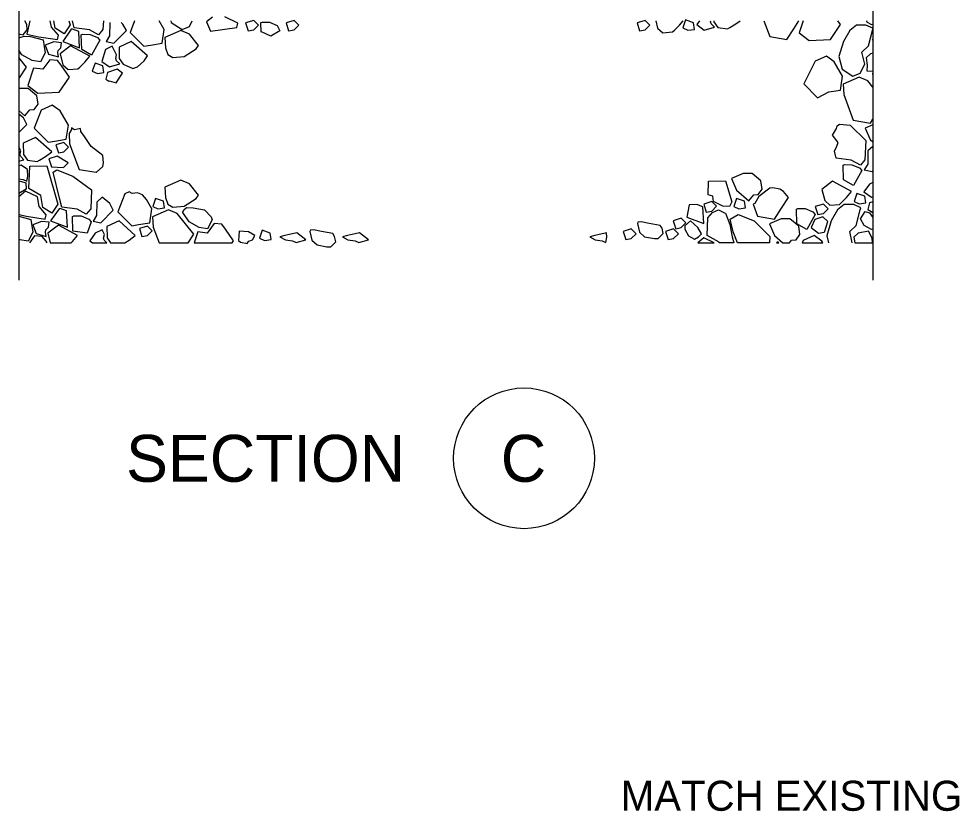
# Model space of a CAD drawing. Extents: x 99862 to 103151, y 100000 to 108153.
# Drawn here: x 101790 to 102291, y 101094 to 101517 of the extents above; entities that cross this region are included whole.
import ezdxf

# ---------------------------------------------------------------- set-up
doc = ezdxf.new("R2010")
doc.units = 0
for name, color, linetype in [('Level 15', 7, 'Continuous'), ('Level 18', 7, 'Continuous'), ('Level 20', 7, 'Continuous')]:
    doc.layers.add(name, color=color, linetype=linetype)

msp = doc.modelspace()

# ---------------------------------------------------------------- linework, layer by layer
at = {"layer": 'Level 15'}
for points in [[(102245.17, 101887.78), (102245.17, 101714.5), (102260.65, 101714.5), (102229.68, 101683.53), (102245.17, 101683.53), (102245.17, 101377.32)], [(101790.17, 101558.07), (101790.17, 101377.32)]]:
    msp.add_lwpolyline(points, dxfattribs=at)
at = {"layer": 'Level 20'}
for p, q in [((102171.05, 101397.32), (102163.29, 101397.32)), ((102190.13, 101397.32), (102172.98, 101397.32))]:
    msp.add_line(p, q, dxfattribs=at)
for points in [[(101790.17, 101508.09), (101790.95, 101508.49), (101792.54, 101508.15), (101794.64, 101510.7), (101794.46, 101513.7), (101793.37, 101515.66)], [(101796.01, 101515.66), (101794.48, 101508.49), (101800.86, 101507.12), (101810.7, 101505.57), (101811.29, 101507.86), (101807.5, 101512.24), (101806.95, 101515.66)], [(101816.87, 101515.66), (101817.48, 101513.51), (101814.37, 101508.63), (101809.5, 101511.74), (101808.86, 101515.66)], [(101835.24, 101515.66), (101835, 101510.95), (101832.65, 101508.1), (101827.78, 101510.84), (101819.7, 101511.89), (101818.74, 101515.66)], [(101838.59, 101514.62), (101838.56, 101507.63), (101836.69, 101504.53), (101840.84, 101503.7), (101847.47, 101510.4), (101845.62, 101513.87), (101844.74, 101514.62)], [(101851.86, 101515.66), (101849.45, 101509.4), (101856.84, 101502.01), (101860.39, 101502.6), (101866.55, 101503.63), (101867.63, 101511.03), (101864.96, 101515.66)], [(101871.15, 101515.66), (101871.38, 101514.77), (101877.14, 101510.92), (101881.06, 101512.62), (101882.58, 101515.66)], [(101893.28, 101517.59), (101890.07, 101515.03), (101892.31, 101510.11), (101906.3, 101512.11), (101906.89, 101514.4), (101899.92, 101517.62)], [(101915.29, 101510.77), (101917.81, 101513.29), (101915.29, 101515.8), (101911.01, 101514.47), (101912.34, 101510.18), (101912.34, 101510.18), (101915.29, 101510.77)], [(101919.19, 101509.57), (101919.04, 101514.65), (101919.78, 101514.94)], [(101919.78, 101514.94), (101923.7, 101514.92), (101927.76, 101513.17), (101929.3, 101510.32), (101924.5, 101507.47), (101919.42, 101509.69)], [(101936.88, 101510.77), (101939.39, 101513.29), (101936.88, 101515.8), (101932.59, 101514.47), (101933.92, 101510.18), (101933.92, 101510.18), (101936.88, 101510.77)], [(102123.79, 101510.77), (102126.3, 101513.29), (102123.79, 101515.8), (102119.5, 101514.47), (102120.83, 101510.18), (102120.83, 101510.18), (102123.79, 101510.77)], [(102129.44, 101515.66), (102130.42, 101511.7), (102133.19, 101509.22), (102138.36, 101509.67), (102139.43, 101510.59), (102142.09, 101513.25), (102144.11, 101515.66)], [(102146.62, 101510.52), (102150.13, 101511.04), (102149.61, 101514.55), (102145.38, 101516.04), (102143.89, 101511.81), (102143.89, 101511.81), (102146.62, 101510.52)], [(102152.81, 101515.66), (102151.28, 101513.57), (102155.3, 101510.61), (102160.73, 101512.27), (102159.06, 101513.97), (102158.66, 101515.07), (102158.79, 101515.66)], [(102160.49, 101515.66), (102160.49, 101515.11), (102162.63, 101512.07), (102167.77, 101511.32), (102169.02, 101511.97), (102172.22, 101513.96), (102174.48, 101515.66)], [(102187.02, 101515.66), (102190.2, 101507.14), (102199.29, 101505.59), (102202.98, 101511.36), (102205.74, 101515.66)], [(102208, 101515.66), (102205.79, 101509.14), (102211.19, 101505.07), (102222.49, 101505.59), (102227.96, 101513.58), (102226.52, 101515.66)], [(102241.9, 101515.66), (102241.67, 101514.99), (102241.67, 101514.99), (102244.4, 101513.71)], [(101885.87, 101502.52), (101881.09, 101508.51), (101876.5, 101510.43), (101868, 101506.67), (101868.3, 101501.2), (101869.61, 101497.68)], [(102245.17, 101511.65), (102241.45, 101513.24), (102236.38, 101513.28), (102232.83, 101510.48), (102229.43, 101504.56), (102227.07, 101496.58), (102228.77, 101489.86), (102234.53, 101486.01), (102238.45, 101487.71), (102240.82, 101492.44), (102239.34, 101498.95), (102242.74, 101502.2), (102244.97, 101510.51), (102245.17, 101511.39)], [(102244.4, 101513.71), (102245.17, 101513.82)], [(101790.17, 101506.58), (101793, 101507.38), (101796.32, 101507.16), (101803.12, 101505.38), (101803.64, 101501.98), (101804.16, 101498.58), (101801.64, 101493.78), (101797.21, 101494.52), (101791.81, 101497.47), (101790.17, 101500.02)], [(101824.18, 101508.4), (101828.1, 101508.38), (101832.16, 101506.63), (101833.41, 101505.22), (101828.91, 101497.32), (101823.68, 101500.24), (101823.44, 101508.11), (101824.18, 101508.4)], [(102245.17, 101505.36), (102245.03, 101505.6), (102245.17, 101505.81)], [(101869.61, 101497.68), (101872.15, 101496.12), (101878.3, 101496.55), (101884.59, 101500.73), (101885.87, 101502.52)], [(101790.17, 101484.54), (101790.59, 101485.2), (101794.28, 101490.96), (101790.17, 101496.12)], [(102245.17, 101498.29), (102243.88, 101498.02), (102241.59, 101495.95), (102242.11, 101492.04), (102241.96, 101488.86), (102245.14, 101488.71), (102245.17, 101488.72)], [(101832, 101487.55), (101835.52, 101488.07), (101835, 101491.58), (101830.76, 101493.07), (101829.27, 101488.83), (101829.27, 101488.83), (101832, 101487.55)], [(101845.49, 101487.69), (101842.57, 101489.75), (101837.47, 101488.05), (101836.51, 101484.43), (101838.16, 101483.51)], [(101838.16, 101483.51), (101838.26, 101483.58), (101842.03, 101482.58), (101845.49, 101487.69)], [(102245.17, 101480.16), (102242.41, 101483.6), (102237.83, 101485.52), (102229.33, 101481.75), (102229.63, 101476.29), (102234.73, 101462.61), (102243.82, 101461.06), (102245.17, 101463.16)], [(102245.17, 101486.94), (102245.08, 101487.64), (102245.17, 101487.66)], [(101790.17, 101467.75), (101793.32, 101465.02), (101795.97, 101468.08), (101798.35, 101468.42), (101800.42, 101471.23), (101799.82, 101475.66), (101795.09, 101479.51), (101790.36, 101479.51), (101790.17, 101479.42)], [(101790.17, 101456.05), (101794.43, 101460.36), (101792.59, 101463.83), (101790.17, 101465.9)], [(102224.62, 101446.14), (102225.95, 101448.71), (102226.73, 101450.82), (102223.63, 101454.65), (102225.74, 101458.13), (102226.1, 101459.67), (102227.37, 101460.52)], [(102227.37, 101460.52), (102232.97, 101459.9), (102241.37, 101451.76), (102240.86, 101441.51), (102238.51, 101438.66), (102233.64, 101441.4), (102225.55, 101442.45), (102224.62, 101446.14)], [(102245.17, 101460.22), (102241.08, 101458.47), (102243.74, 101452.27), (102245.17, 101451.04)], [(101818.25, 101457.64), (101816.93, 101455.6), (101817.23, 101450.13), (101822.33, 101436.45), (101831.42, 101434.9), (101831.5, 101435.03)], [(101831.5, 101435.03), (101834.96, 101437.92), (101835.23, 101439.91), (101834.9, 101443.89), (101828.71, 101448.64), (101825.09, 101453.92), (101823.28, 101456.66), (101823.11, 101458.21), (101819.88, 101457.48), (101818.32, 101458.53), (101818.25, 101457.64)], [(101814.2, 101445.77), (101816.71, 101448.28), (101814.2, 101450.79), (101809.91, 101449.46), (101811.24, 101445.18), (101811.24, 101445.18), (101814.2, 101445.77)], [(101790.17, 101440.76), (101792.86, 101441.59), (101791.19, 101443.28), (101790.79, 101444.39), (101791.21, 101446.33), (101790.17, 101448.43)], [(102245.17, 101448.66), (102242.49, 101446.28), (102242.45, 101439.23), (102240.58, 101436.12), (102244.73, 101435.29), (102245.17, 101435.73)], [(101813.95, 101437.42), (101816.46, 101439.94), (101810.52, 101443.45), (101806.23, 101442.12), (101807.57, 101437.84), (101807.57, 101437.84), (101813.83, 101437.37)], [(101790.17, 101431.32), (101792.54, 101430.99), (101794.49, 101430.14), (101794.98, 101432.84), (101794.75, 101436.39), (101791.5, 101438.68), (101790.17, 101438.24)], [(102230.03, 101438.96), (102233.96, 101438.93), (102238.02, 101437.19), (102239.26, 101435.78), (102234.76, 101427.88), (102229.54, 101430.8), (102229.3, 101438.67), (102230.03, 101438.96)], [(101790.17, 101429.78), (101791.1, 101430.07), (101793.94, 101429.22), (101794.16, 101425.89), (101790.17, 101423.52)], [(101885.87, 101422.73), (101881.09, 101428.72), (101876.5, 101430.64), (101868, 101426.87), (101868.3, 101421.41), (101869.61, 101417.89)], [(102157.31, 101422.9), (102157.56, 101430.11), (102166.72, 101430.41), (102169.94, 101419.06)], [(102245.17, 101429.47), (102243.29, 101428.54), (102240.34, 101424.51), (102244.36, 101421.55), (102245.17, 101421.8)], [(101790.17, 101412.41), (101794.32, 101411.52), (101804.16, 101409.97), (101804.75, 101412.26), (101800.96, 101416.64), (101800.13, 101421.83), (101793.7, 101424.86), (101790.17, 101421.86)], [(101848.92, 101424.45), (101846.61, 101423.41), (101842.91, 101413.8), (101850.31, 101406.41), (101853.85, 101407), (101860.01, 101408.03), (101861.1, 101415.43), (101858.27, 101420.33)], [(101858.27, 101420.33), (101856.06, 101422.81), (101853.42, 101423.98), (101850.64, 101423.61), (101848.92, 101424.45)], [(102197.59, 101424.71), (102195.64, 101425.91), (102191.84, 101426.6), (102190.17, 101426.47), (102184.46, 101421.94), (102182.17, 101418.18), (102181.3, 101417.87)], [(102181.3, 101417.87), (102183.66, 101411.54), (102192.75, 101409.99), (102196.44, 101415.76), (102200.14, 101421.52), (102197.59, 101424.71)], [(101864.24, 101415.41), (101867.75, 101415.93), (101867.23, 101419.45), (101863, 101420.93), (101861.51, 101416.7), (101861.51, 101416.7), (101864.24, 101415.41)], [(101869.61, 101417.89), (101872.15, 101416.33), (101878.3, 101416.76), (101884.59, 101420.94), (101885.87, 101422.73)], [(102159.38, 101414.25), (102161.89, 101416.76), (102159.38, 101419.27), (102155.09, 101417.94), (102156.42, 101413.66), (102156.42, 101413.66), (102159.38, 101414.25)], [(102169.94, 101419.06), (102168.72, 101416.66), (102165.15, 101416.91), (102160.2, 101419.39), (102159.92, 101422.17), (102157.31, 101422.9)], [(102173.8, 101415.41), (102177.31, 101415.93), (102176.79, 101419.45), (102172.56, 101420.93), (102171.07, 101416.7), (102171.07, 101416.7), (102173.8, 101415.41)], [(102237.86, 101418.11), (102241.37, 101418.63), (102240.85, 101422.14), (102236.62, 101423.63), (102235.13, 101419.39), (102235.13, 101419.39), (102237.86, 101418.11)], [(102245.17, 101419.22), (102243.33, 101418.61), (102242.37, 101414.99), (102245.17, 101413.43)], [(101880.4, 101397.32), (101883.34, 101401.9), (101874.55, 101412.91), (101869.96, 101414.84), (101861.46, 101411.07), (101861.76, 101405.6), (101864.85, 101397.32)], [(101877.6, 101413.63), (101878.14, 101414.94), (101879.46, 101416.17), (101883, 101415.86), (101889.14, 101414.83), (101892.65, 101411.18), (101893.2, 101409.49)], [(102157.21, 101410.58), (102159.76, 101413.44), (102162.99, 101414.87), (102166.48, 101413.08), (102166.58, 101413.1)], [(102205.16, 101415.54), (102209.09, 101415.51), (102213.14, 101413.76), (102214.39, 101412.35), (102209.89, 101404.45), (102204.66, 101407.37), (102204.42, 101415.24), (102205.16, 101415.54)], [(102218.75, 101412.93), (102221.26, 101415.45), (102218.75, 101417.96), (102214.46, 101416.63), (102215.79, 101412.34), (102215.79, 101412.34), (102218.75, 101412.93)], [(102238.68, 101416.03), (102234.91, 101417.64), (102229.84, 101417.69), (102226.29, 101414.88), (102222.89, 101408.96), (102220.53, 101400.98), (102221.46, 101397.32)], [(102234.17, 101397.32), (102232.8, 101403.35), (102236.2, 101406.6), (102238.43, 101414.91), (102238.68, 101416.03)], [(101790.17, 101411.46), (101796.58, 101409.78), (101797.1, 101406.38), (101797.62, 101402.98), (101795.1, 101398.18), (101790.67, 101398.92), (101790.17, 101399.2)], [(101819.5, 101411.66), (101823.43, 101411.63), (101827.49, 101409.89), (101828.73, 101408.47), (101826.59, 101402.46), (101819, 101403.49), (101818.76, 101411.37), (101819.5, 101411.66)], [(101893.2, 101409.49), (101890.7, 101404.72), (101886.27, 101405.46), (101880.87, 101408.41), (101877.62, 101413.44), (101877.6, 101413.63)], [(102143.06, 101405.4), (102145.58, 101407.91), (102143.06, 101410.43), (102138.78, 101409.09), (102140.11, 101404.81), (102140.11, 101404.81), (102143.06, 101405.4)], [(102163.29, 101397.32), (102163.25, 101397.58), (102156.89, 101401.28), (102157.21, 101410.58)], [(102166.58, 101413.1), (102168.88, 101406.98), (102170.13, 101400.55), (102171.05, 101397.32)], [(102172.98, 101397.32), (102170.73, 101403.19), (102169.04, 101409.84), (102173.37, 101412.39), (102181.97, 101409.07), (102190.3, 101400.69), (102190.13, 101397.32)], [(102200.68, 101397.32), (102201.82, 101398.64), (102204.2, 101398.98), (102206.27, 101401.79), (102205.68, 101406.22), (102200.95, 101410.07), (102196.22, 101410.07), (102190.01, 101407.4), (102192.67, 101401.2), (102197.17, 101397.32)], [(102219.43, 101402.97), (102221.06, 101408.61), (102218.55, 101411.12), (102214.26, 101409.79), (102212.26, 101405.5), (102216.2, 101402.44), (102219.16, 101403.03)], [(102245.17, 101404.65), (102244.33, 101404.46), (102240.48, 101406.45), (102238.49, 101410), (102241.11, 101414.03), (102243.4, 101413.29), (102245.14, 101410.81), (102245.17, 101410.82)], [(101818.04, 101397.32), (101818.75, 101398.03), (101821.43, 101401.23), (101811.23, 101406.73), (101805.64, 101402.36), (101806.87, 101397.32)], [(101837.13, 101397.32), (101835.72, 101398.75), (101835.32, 101399.86), (101835.74, 101401.8), (101834.55, 101404.19), (101830.9, 101402.38), (101827.94, 101398.35), (101829.35, 101397.32)], [(101846.59, 101397.32), (101848.88, 101398.74), (101852.22, 101401.24), (101843.54, 101408.93), (101837.09, 101405.94), (101837.16, 101399.89), (101838.96, 101397.32)], [(101858.73, 101401.24), (101861.24, 101403.75), (101858.73, 101406.26), (101854.44, 101404.93), (101855.77, 101400.65), (101855.77, 101400.65), (101858.73, 101401.24)], [(101903.9, 101397.32), (101904.62, 101398.36), (101900.27, 101404.64), (101898.27, 101407.16), (101894.21, 101407.59), (101890.44, 101402.49), (101885.56, 101403.08), (101883.6, 101397.32)], [(101958.42, 101400.7), (101957.44, 101402.27), (101951.47, 101403.32), (101947.19, 101404.14), (101945.52, 101404.01), (101945.23, 101403.27)], [(102116.44, 101399.64), (102118.96, 101402.16), (102116.44, 101404.67), (102112.16, 101403.34), (102113.49, 101399.05), (102113.49, 101399.05), (102116.44, 101399.64)], [(102132.86, 101405.04), (102131.88, 101406.61), (102125.92, 101407.66), (102121.64, 101408.48), (102119.96, 101408.35), (102119.67, 101407.61)], [(102119.67, 101407.61), (102120.8, 101403.02), (102123.57, 101400.54), (102128.74, 101399.52), (102130.85, 101399.57), (102133.51, 101402.23), (102132.86, 101405.04)], [(102139.01, 101399.64), (102141.53, 101402.16), (102139.01, 101404.67), (102134.73, 101403.34), (102136.06, 101399.05), (102136.06, 101399.05), (102139.01, 101399.64)], [(102152.33, 101400.54), (102153.82, 101402.05), (102151.98, 101405.53), (102147.93, 101408.99), (102144.95, 101406.34), (102144.94, 101404.5)], [(102144.94, 101404.5), (102146.88, 101401.07), (102150.17, 101399.2), (102152.33, 101400.54)], [(101805.21, 101397.32), (101804.67, 101398.1), (101802.67, 101400.62), (101798.61, 101401.05), (101795.84, 101397.32)], [(101911.96, 101397.02), (101912, 101397.22), (101912.71, 101398.15), (101914.58, 101398.84), (101915.95, 101401.14), (101912.45, 101403.24), (101907.47, 101403.56), (101907.15, 101398.58), (101908.31, 101397.59)], [(101921.06, 101398.49), (101924.58, 101399.01), (101924.06, 101402.52), (101922.68, 101403), (101919.82, 101404.01), (101918.33, 101399.78), (101918.33, 101399.78), (101921.06, 101398.49)], [(101929.26, 101400.53), (101932.15, 101398.92), (101935.92, 101398.41), (101937.88, 101397.56), (101943.12, 101398.88), (101938.21, 101402.63)], [(101938.21, 101402.63), (101937.55, 101402.46), (101933.56, 101401.51), (101931.95, 101401.12), (101929.26, 101400.53)], [(101945.23, 101403.27), (101946.35, 101398.68), (101949.12, 101396.2), (101954.3, 101395.18), (101956.41, 101395.23), (101959.07, 101397.89), (101958.42, 101400.7)], [(101962.63, 101400.53), (101965.52, 101398.92), (101969.29, 101398.41), (101971.25, 101397.56), (101976.49, 101398.88), (101971.58, 101402.63)], [(101971.58, 101402.63), (101970.91, 101402.46), (101966.93, 101401.51), (101965.31, 101401.12), (101962.63, 101400.53)], [(102094.32, 101400.53), (102097.21, 101398.92), (102100.98, 101398.41), (102102.94, 101397.56), (102103.42, 101400.25), (102103.27, 101402.63)], [(102103.27, 101402.63), (102102.61, 101402.46), (102098.63, 101401.51), (102097.01, 101401.12), (102094.32, 101400.53)], [(102160.61, 101397.32), (102155.03, 101399.95), (102151.93, 101397.32)], [(102218.5, 101397.32), (102217.99, 101398.2), (102213.85, 101401.16), (102207.94, 101398.5), (102207.48, 101397.32)], [(102244.99, 101397.32), (102244.84, 101399.73), (102242.74, 101403.53), (102237.34, 101402.42), (102235.05, 101400.35), (102235.45, 101397.32)], [(101806.87, 101397.32), (101818.04, 101397.32)], [(101829.35, 101397.32), (101837.13, 101397.32)], [(101838.96, 101397.32), (101846.59, 101397.32)], [(101864.85, 101397.32), (101876.15, 101397.32), (101880.4, 101397.32)], [(101883.6, 101397.32), (101894.27, 101397.32), (101903.9, 101397.32)], [(101908.31, 101397.59), (101911.96, 101397.02)], [(102151.93, 101397.32), (102160.61, 101397.32)], [(102195.02, 101397.32), (102194.39, 101397.85), (102193.79, 101397.32)], [(102193.79, 101397.32), (102195.02, 101397.32)], [(102197.17, 101397.32), (102200.68, 101397.32)], [(102207.48, 101397.32), (102218.5, 101397.32)], [(102235.45, 101397.32), (102244.99, 101397.32)]]:
    msp.add_lwpolyline(points, dxfattribs=at)
for points in [[(101818.14, 101511.07), (101813.56, 101504.57), (101822.58, 101501.17), (101822.06, 101509.96), (101818.73, 101511.22), (101818.73, 101511.22)], [(101811.14, 101499.8), (101812.55, 101501.21), (101812.84, 101503.87), (101808.79, 101504.32), (101804.12, 101502.54), (101805.9, 101497.87), (101811.36, 101496.33), (101810.88, 101498.66)], [(101853.43, 101491.03), (101856.88, 101494.34), (101858.76, 101496.84), (101850.08, 101504.53), (101843.63, 101501.54), (101843.7, 101495.49), (101845.83, 101492.45), (101850.97, 101490.23)], [(101822.63, 101490.97), (101825.29, 101493.63), (101827.97, 101496.83), (101817.77, 101502.33), (101812.18, 101497.96), (101813.62, 101492.08), (101816.39, 101489.6), (101821.56, 101490.05)], [(101841.86, 101495.46), (101842.28, 101497.4), (101839.94, 101502.09), (101836.29, 101500.28), (101834.48, 101493.95), (101838.5, 101491), (101843.93, 101492.66), (101842.26, 101494.35)], [(101802.94, 101489.76), (101798.07, 101490.35), (101794.96, 101481.18), (101800.36, 101477.12), (101811.67, 101477.63), (101817.13, 101485.62), (101812.77, 101491.9), (101810.78, 101494.42), (101806.71, 101494.85)], [(102228.96, 101486.12), (102224.53, 101493.8), (102220.39, 101496.76), (102214.48, 101494.1), (102208.28, 101481.98), (102215.67, 101474.59), (102221.72, 101477.69), (102227.88, 101478.72)], [(101816.57, 101459.96), (101812.13, 101467.64), (101807.99, 101470.6), (101802.08, 101467.94), (101798.38, 101458.33), (101805.78, 101450.94), (101809.32, 101451.53), (101815.48, 101452.56)], [(101801.15, 101441.29), (101804.35, 101443.27), (101807.69, 101445.77), (101799.01, 101453.46), (101792.56, 101450.47), (101792.63, 101444.42), (101794.76, 101441.38), (101799.9, 101440.63)], [(101795.97, 101438.1), (101805.14, 101438.4), (101810.94, 101417.91), (101807.83, 101413.04), (101802.96, 101416.14), (101801.92, 101422.5), (101795.57, 101426.19)], [(101810.42, 101436.13), (101819.01, 101432.8), (101828.97, 101425.6), (101828.46, 101415.35), (101826.11, 101412.5), (101821.24, 101415.24), (101813.16, 101416.29), (101811.93, 101421.13), (101808.43, 101434.93)], [(102186.09, 101425.93), (102185.5, 101430.37), (102180.77, 101434.21), (102176.04, 101434.21), (102169.83, 101431.55), (102172.49, 101425.34), (102178.99, 101419.72), (102181.64, 101422.79), (102184.02, 101423.12)], [(102228.49, 101418.71), (102231.15, 101421.37), (102233.83, 101424.56), (102223.63, 101430.07), (102218.03, 101425.69), (102219.48, 101419.82), (102222.25, 101417.34), (102227.42, 101417.78)], [(101840.52, 101414.71), (101838.68, 101418.18), (101834.62, 101421.64), (101831.65, 101419), (101831.61, 101411.94), (101829.75, 101408.83), (101833.89, 101408.01)], [(101811.6, 101415.47), (101807.02, 101408.97), (101816.04, 101405.57), (101815.52, 101414.37), (101812.2, 101415.62), (101812.2, 101415.62)], [(102147.22, 101417.54), (102146.12, 101411.04), (102155.13, 101407.64), (102154.62, 101416.44), (102151.29, 101417.69), (102151.29, 101417.69)], [(101804.6, 101404.2), (101806.01, 101405.61), (101806.3, 101408.27), (101802.25, 101408.72), (101797.58, 101406.94), (101799.36, 101402.27), (101804.82, 101400.73), (101804.34, 101403.06)]]:
    msp.add_lwpolyline(points, close=True, dxfattribs=at)
msp.add_circle((102059.3, 101282.5), 37.5, dxfattribs=at)

# ---------------------------------------------------------------- texts
at = {"layer": 'Level 18'}
msp.add_text('MATCH EXISTING', height=16, dxfattribs=at).set_placement((102110.85, 101094.7))
at = {"layer": 'Level 20'}
for s, p in [('SECTION', (101847.31, 101269.98)), ('C', (102046.93, 101269.98))]:
    msp.add_text(s, height=25, dxfattribs=at).set_placement(p)

doc.saveas('drawing.dxf')
